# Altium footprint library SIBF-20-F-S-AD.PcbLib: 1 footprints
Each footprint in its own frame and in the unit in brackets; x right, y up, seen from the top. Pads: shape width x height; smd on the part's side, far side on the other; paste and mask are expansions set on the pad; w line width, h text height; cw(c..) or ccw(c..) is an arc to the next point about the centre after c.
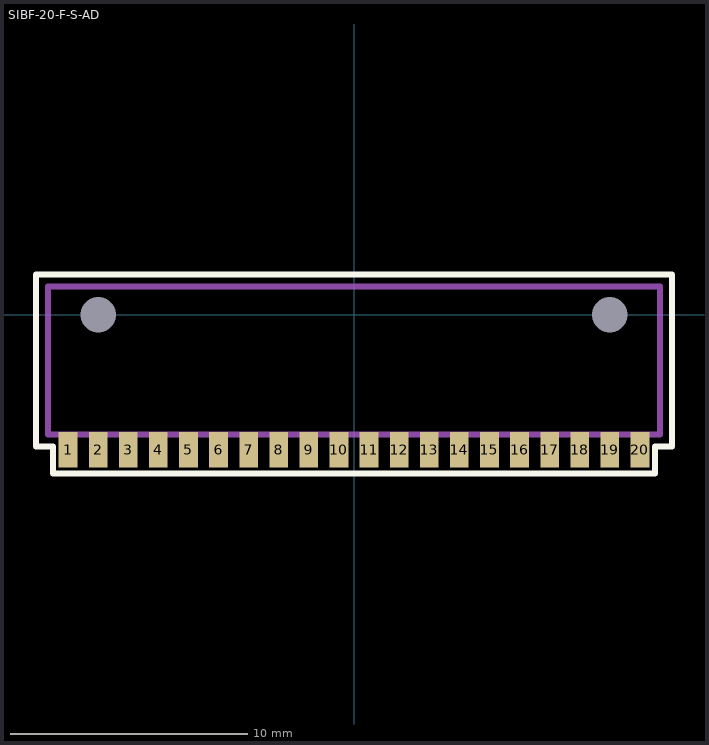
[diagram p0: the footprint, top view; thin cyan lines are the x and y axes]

## SIBF-20-F-S-AD [mil]
pads (22):
  rect 31x59 smd mask+2: 1(-475,-224.5) 2(-425,-224.5) 3(-375,-224.5) 4(-325,-224.5) 5(-275,-224.5) 6(-225,-224.5) 7(-175,-224.5) 8(-125,-224.5) 9(-75,-224.5) 10(-25,-224.5) 11(25,-224.5) 12(75,-224.5) 13(125,-224.5) 14(175,-224.5) 15(225,-224.5) 16(275,-224.5) 17(325,-224.5) 18(375,-224.5) 19(425,-224.5) 20(475,-224.5)
  round 0 / inner rrect0% 0x0 / far side rrect0% 0x0 hole 59 unplated: 21(-425,0) 22(425,0)
Top Overlay:
  lines w10: -528.5,-219 -528.5,67 528.5,67 528.5,-219 500,-219 500,-264 -500,-264 -500,-219 -528.5,-219
Mechanical 1:
  lines w10: -508.5,-199 -508.5,47 508.5,47 508.5,-199 -508.5,-199
  text "J1" at -17.57,-99.52 h30
3D body: height 188.37, standoff -50.41, extent -508.49,-233.99 508.51,57.35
